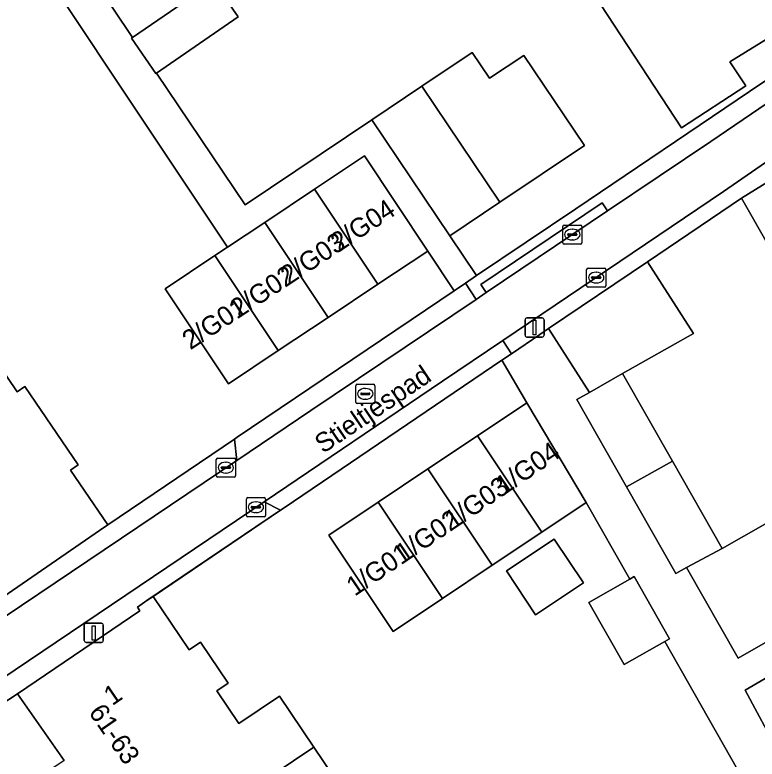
# Model space of a CAD drawing. Extents: x 159888 to 160761, y 384031 to 384750.
# Drawn here: x 160437.78 to 160476.49, y 384295.49 to 384334.29 of the extents above; entities that cross this region are included whole.
import ezdxf

# ---------------------------------------------------------------- set-up
doc = ezdxf.new("R2010")
doc.units = 0
for name, color, linetype in [('IMGEO_Erf', 7, 'Continuous'), ('IMGEO_Kolk', 7, 'Continuous'), ('IMGEO_Lichtmast', 7, 'Continuous'), ('IMGEO_Muur', 7, 'Continuous'), ('IMGEO_Openbare_ruimte_label', 7, 'Continuous'), ('IMGEO_Pand', 7, 'Continuous'), ('IMGEO_Pand_nummerreeks', 7, 'Continuous'), ('IMGEO_Rijbaan_lokaal_open', 7, 'Continuous'), ('IMGEO_Rioolput', 7, 'Continuous'), ('IMGEO_Voetpad_open', 7, 'Continuous')]:
    doc.layers.add(name, color=color, linetype=linetype)

msp = doc.modelspace()

# ---------------------------------------------------------------- linework, layer by layer
at = {"layer": 'IMGEO_Erf'}
for points in [[(160456.666, 384356.276), (160458.578, 384353.848), (160460.552, 384351.342), (160461.672, 384352.224), (160468.506, 384356.754), (160471.872, 384351.597), (160475.173, 384346.539), (160478.474, 384341.481), (160481.974, 384336.119), (160475.071, 384331.85), (160475.896, 384330.595), (160472.553, 384328.397), (160468.334, 384334.813), (160471.677, 384337.011), (160468.359, 384342.057), (160465.04, 384347.104), (160461.502, 384344.777), (160458.334, 384349.595), (160454.817, 384346.825), (160452.803, 384349.382), (160452.769, 384349.425), (160446.476, 384344.469), (160444.638, 384346.803)], [(160487.032, 384315.964), (160485.504, 384318.66), (160484.117, 384321.107), (160479.288, 384318.371), (160478.097, 384320.473), (160477.012, 384322.387), (160475.678, 384324.741), (160470.773, 384321.422), (160473.178, 384317.676), (160469.475, 384315.595), (160472.079, 384311.028), (160474.675, 384306.475), (160478.184, 384308.475), (160480.847, 384303.804), (160490.773, 384309.494), (160489.194, 384312.28), (160484.426, 384309.578), (160484.38, 384309.552), (160482.675, 384308.586), (160481.62, 384310.447), (160483.325, 384311.413), (160482.275, 384313.267)], [(160492.415, 384304.215), (160490.486, 384307.61), (160475.868, 384299.074), (160477.633, 384295.818), (160478.853, 384296.511)], [(160464.938, 384303.017), (160463.416, 384305.296), (160465.906, 384306.959), (160467.429, 384304.681)]]:
    msp.add_lwpolyline(points, close=True, dxfattribs=at)
for points in [[(160434.938, 384346.488), (160443.918, 384333.117), (160448.156, 384336.03), (160449.423, 384334.187), (160445.166, 384331.26), (160449.784, 384324.384), (160456.397, 384328.826), (160459.01, 384330.581), (160461.626, 384332.337), (160462.527, 384330.994), (160464.329, 384332.179), (160467.485, 384327.479), (160463.08, 384324.521), (160460.466, 384322.766), (160461.863, 384320.697), (160467.03, 384324.187), (160476.088, 384330.303), (160483.657, 384335.415)], [(160436.409, 384316.824), (160437.899, 384314.639), (160438.308, 384314.912), (160441.08, 384310.832), (160440.677, 384310.562), (160442.622, 384307.708), (160449.231, 384312.166), (160449.382, 384312.268), (160460.694, 384319.908), (160459.314, 384321.98), (160456.715, 384320.249), (160454.116, 384318.518), (160451.516, 384316.786), (160448.917, 384315.055), (160445.615, 384320.013), (160448.214, 384321.744), (160448.878, 384322.186), (160435.234, 384342.622)], [(160482.685, 384282.232), (160471.687, 384301.627), (160469.561, 384300.415), (160467.711, 384303.659), (160469.845, 384304.875), (160467.581, 384308.868), (160465.262, 384307.319), (160462.677, 384305.592), (160460.091, 384303.865), (160457.506, 384302.138), (160454.148, 384307.164), (160456.734, 384308.891), (160459.319, 384310.618), (160461.905, 384312.346), (160464.49, 384314.073), (160463.178, 384316.282), (160451.825, 384308.598), (160451.63, 384308.466), (160444.987, 384303.97), (160446.868, 384301.186), (160447.463, 384301.589), (160448.908, 384299.452), (160448.312, 384299.049), (160449.468, 384297.338), (160451.59, 384298.767), (160453.375, 384296.116), (160454.889, 384293.868)], [(160440.346, 384295.421), (160437.919, 384298.895), (160432.977, 384295.669), (160463.867, 384250)]]:
    msp.add_lwpolyline(points, dxfattribs=at)
at = {"layer": 'IMGEO_Kolk'}
for p, q in [((160466.428, 384323.336), (160467.28, 384323.336)), ((160466.353, 384322.41), (160466.353, 384323.262)), ((160466.841, 384323.116), (160466.866, 384323.116)), ((160467.354, 384323.262), (160467.354, 384322.41)), ((160466.612, 384322.83), (160466.612, 384322.842)), ((160467.05, 384322.793), (160466.652, 384322.793)), ((160466.655, 384322.879), (160467.053, 384322.879)), ((160466.864, 384322.556), (160466.839, 384322.556)), ((160467.096, 384322.842), (160467.096, 384322.83)), ((160467.28, 384322.336), (160466.428, 384322.336)), ((160467.601, 384320.167), (160467.601, 384321.019)), ((160467.676, 384321.093), (160468.528, 384321.093)), ((160468.602, 384321.019), (160468.602, 384320.167)), ((160467.86, 384320.587), (160467.86, 384320.599)), ((160467.903, 384320.636), (160468.301, 384320.636)), ((160468.089, 384320.873), (160468.114, 384320.873)), ((160468.344, 384320.599), (160468.344, 384320.587)), ((160468.298, 384320.55), (160467.9, 384320.55)), ((160468.112, 384320.313), (160468.087, 384320.313)), ((160468.528, 384320.093), (160467.676, 384320.093)), ((160448.284, 384310.259), (160448.284, 384311.111)), ((160448.359, 384311.185), (160449.211, 384311.185)), ((160448.772, 384310.965), (160448.797, 384310.965)), ((160449.285, 384311.111), (160449.285, 384310.259)), ((160448.543, 384310.679), (160448.543, 384310.691)), ((160448.981, 384310.642), (160448.583, 384310.642)), ((160448.586, 384310.728), (160448.984, 384310.728)), ((160449.027, 384310.691), (160449.027, 384310.679)), ((160449.211, 384310.185), (160448.359, 384310.185)), ((160448.795, 384310.405), (160448.77, 384310.405)), ((160449.853, 384308.194), (160449.853, 384309.046)), ((160449.928, 384309.12), (160450.78, 384309.12)), ((160450.854, 384309.046), (160450.854, 384308.194)), ((160450.112, 384308.614), (160450.112, 384308.626)), ((160450.55, 384308.577), (160450.152, 384308.577)), ((160450.155, 384308.663), (160450.553, 384308.663)), ((160450.341, 384308.9), (160450.366, 384308.9)), ((160450.596, 384308.626), (160450.596, 384308.614)), ((160450.364, 384308.34), (160450.339, 384308.34)), ((160450.78, 384308.12), (160449.928, 384308.12))]:
    msp.add_line(p, q, dxfattribs=at)
for points in [[(160466.428, 384323.336), (160467.28, 384323.336)], [(160466.353, 384322.41), (160466.353, 384323.262)], [(160467.354, 384323.262), (160467.354, 384322.41)], [(160467.28, 384322.336), (160466.428, 384322.336)], [(160467.601, 384320.167), (160467.601, 384321.019)], [(160467.676, 384321.093), (160468.528, 384321.093)], [(160468.602, 384321.019), (160468.602, 384320.167)], [(160468.528, 384320.093), (160467.676, 384320.093)], [(160448.284, 384310.259), (160448.284, 384311.111)], [(160448.359, 384311.185), (160449.211, 384311.185)], [(160449.285, 384311.111), (160449.285, 384310.259)], [(160449.211, 384310.185), (160448.359, 384310.185)], [(160449.853, 384308.194), (160449.853, 384309.046)], [(160449.928, 384309.12), (160450.78, 384309.12)], [(160450.854, 384309.046), (160450.854, 384308.194)], [(160450.78, 384308.12), (160449.928, 384308.12)]]:
    msp.add_lwpolyline(points, dxfattribs=at)
for centre, radius, start, end in [((160466.43, 384323.26), 0.0765, 91.552, 178.448), ((160466.43, 384323.26), 0.0765, 91.552, 178.448), ((160467.278, 384323.26), 0.0765, 1.552, 88.448), ((160467.278, 384323.26), 0.0765, 1.552, 88.448), ((160466.652, 384322.839), 0.0403, 85.8775, 175.7526), ((160466.649, 384322.829), 0.0366, 178.938, 274.7102), ((160467.053, 384322.836), 0.043, 264.8664, 352.4533), ((160467.057, 384322.841), 0.0386, 1.7309, 96.639), ((160466.43, 384322.412), 0.0765, 181.552, 268.448), ((160466.43, 384322.412), 0.0765, 181.552, 268.448), ((160467.278, 384322.412), 0.0765, 271.552, 358.448), ((160467.278, 384322.412), 0.0765, 271.552, 358.448), ((160467.678, 384321.017), 0.0765, 91.552, 178.448), ((160467.678, 384321.017), 0.0765, 91.552, 178.448), ((160468.526, 384321.017), 0.0765, 1.552, 88.448), ((160468.526, 384321.017), 0.0765, 1.552, 88.448), ((160467.9, 384320.596), 0.0403, 85.8775, 175.7526), ((160467.897, 384320.586), 0.0366, 178.938, 274.7102), ((160468.301, 384320.593), 0.043, 264.8664, 352.4533), ((160468.305, 384320.598), 0.0386, 1.7309, 96.639), ((160467.678, 384320.169), 0.0765, 181.552, 268.448), ((160467.678, 384320.169), 0.0765, 181.552, 268.448), ((160468.526, 384320.169), 0.0765, 271.552, 358.448), ((160468.526, 384320.169), 0.0765, 271.552, 358.448), ((160448.361, 384311.109), 0.0765, 91.552, 178.448), ((160448.361, 384311.109), 0.0765, 91.552, 178.448), ((160449.209, 384311.109), 0.0765, 1.552, 88.448), ((160449.209, 384311.109), 0.0765, 1.552, 88.448), ((160448.583, 384310.688), 0.0403, 85.8775, 175.7526), ((160448.58, 384310.678), 0.0366, 178.938, 274.7102), ((160448.984, 384310.685), 0.043, 264.8664, 352.4533), ((160448.988, 384310.69), 0.0386, 1.7309, 96.639), ((160448.361, 384310.261), 0.0765, 181.552, 268.448), ((160448.361, 384310.261), 0.0765, 181.552, 268.448), ((160449.209, 384310.261), 0.0765, 271.552, 358.448), ((160449.209, 384310.261), 0.0765, 271.552, 358.448), ((160449.93, 384309.044), 0.0765, 91.552, 178.448), ((160449.93, 384309.044), 0.0765, 91.552, 178.448), ((160450.778, 384309.044), 0.0765, 1.552, 88.448), ((160450.778, 384309.044), 0.0765, 1.552, 88.448), ((160450.152, 384308.623), 0.0403, 85.8775, 175.7526), ((160450.149, 384308.613), 0.0366, 178.938, 274.7102), ((160450.553, 384308.62), 0.043, 264.8664, 352.4533), ((160450.557, 384308.625), 0.0386, 1.7309, 96.639), ((160449.93, 384308.196), 0.0765, 181.552, 268.448), ((160449.93, 384308.196), 0.0765, 181.552, 268.448), ((160450.778, 384308.196), 0.0765, 271.552, 358.448), ((160450.778, 384308.196), 0.0765, 271.552, 358.448)]:
    msp.add_arc(centre, radius, start, end, dxfattribs=at)
for centre, major_axis, ratio, start_param, end_param in [((160466.84, 384322.836), (-0.387, 0.002), 0.722429, 4.712389, 7.853982), ((160466.865, 384322.836), (-0.39, 0.002), 0.717154, 1.570796, 4.712389), ((160468.088, 384320.593), (-0.387, 0.002), 0.722429, 4.712389, 7.853982), ((160468.113, 384320.593), (-0.39, 0.002), 0.717154, 1.570796, 4.712389), ((160448.771, 384310.685), (-0.387, 0.002), 0.722429, 4.712389, 7.853982), ((160448.796, 384310.685), (-0.39, 0.002), 0.717154, 1.570796, 4.712389), ((160450.34, 384308.62), (-0.387, 0.002), 0.722429, 4.712389, 7.853982), ((160450.365, 384308.62), (-0.39, 0.002), 0.717154, 1.570796, 4.712389)]:
    msp.add_ellipse(centre, major_axis=major_axis, ratio=ratio, start_param=start_param, end_param=end_param, dxfattribs=at)
at = {"layer": 'IMGEO_Lichtmast'}
for p, q in [((160464.387, 384317.593), (160464.387, 384318.393)), ((160464.387, 384318.393), (160464.387, 384317.593)), ((160464.487, 384318.493), (160465.277, 384318.493)), ((160465.277, 384318.493), (160464.487, 384318.493)), ((160465.377, 384318.393), (160465.377, 384317.593)), ((160465.377, 384317.593), (160465.377, 384318.393)), ((160465.277, 384317.493), (160464.487, 384317.493)), ((160464.487, 384317.493), (160465.277, 384317.493)), ((160441.4, 384301.669), (160441.4, 384302.469)), ((160441.4, 384302.469), (160441.4, 384301.669)), ((160441.5, 384302.569), (160442.29, 384302.569)), ((160442.29, 384302.569), (160441.5, 384302.569)), ((160442.39, 384302.469), (160442.39, 384301.669)), ((160442.39, 384301.669), (160442.39, 384302.469)), ((160442.29, 384301.569), (160441.5, 384301.569)), ((160441.5, 384301.569), (160442.29, 384301.569))]:
    msp.add_line(p, q, dxfattribs=at)
for points in [[(160464.807, 384318.368), (160464.957, 384318.368), (160464.957, 384317.618), (160464.807, 384317.618), (160464.807, 384318.368)], [(160441.82, 384302.444), (160441.97, 384302.444), (160441.97, 384301.694), (160441.82, 384301.694), (160441.82, 384302.444)]]:
    msp.add_lwpolyline(points, dxfattribs=at)
for centre, start, end in [((160464.487, 384318.393), 90, 180), ((160464.487, 384318.393), 90, 180), ((160465.277, 384318.393), 0, 90), ((160465.277, 384318.393), 360, 90), ((160464.487, 384317.593), 180, 270), ((160464.487, 384317.593), 180, 270), ((160465.277, 384317.593), 270, 0), ((160465.277, 384317.593), 270, 0), ((160441.5, 384302.469), 90, 180), ((160441.5, 384302.469), 90, 180), ((160442.29, 384302.469), 0, 90), ((160442.29, 384302.469), 360, 90), ((160441.5, 384301.669), 180, 270), ((160441.5, 384301.669), 180, 270), ((160442.29, 384301.669), 270, 0), ((160442.29, 384301.669), 270, 0)]:
    msp.add_arc(centre, 0.1, start, end, dxfattribs=at)
at = {"layer": 'IMGEO_Muur'}
for points in [[(160476.088, 384330.303), (160467.03, 384324.187)], [(160465.616, 384317.932), (160475.678, 384324.741)], [(160449.231, 384312.166), (160442.188, 384307.409)], [(160449.382, 384312.268), (160449.231, 384312.166)], [(160451.825, 384308.598), (160451.63, 384308.466)], [(160451.63, 384308.466), (160444.669, 384303.755)]]:
    msp.add_lwpolyline(points, dxfattribs=at)
at = {"layer": 'IMGEO_Pand'}
for points in [[(160481.974, 384336.119), (160478.474, 384341.481), (160471.677, 384337.011), (160468.334, 384334.813), (160472.553, 384328.397), (160475.896, 384330.595), (160475.071, 384331.85)], [(160443.918, 384333.117), (160443.863, 384333.079), (160445.13, 384331.236), (160445.166, 384331.26), (160449.423, 384334.187), (160448.156, 384336.03)], [(160464.329, 384332.179), (160462.527, 384330.994), (160461.626, 384332.337), (160459.01, 384330.581), (160463.08, 384324.521), (160467.485, 384327.479)], [(160488.821, 384326.551), (160486.16, 384331.218), (160475.678, 384324.741), (160477.012, 384322.387), (160478.097, 384320.473)], [(160459.01, 384330.581), (160456.397, 384328.826), (160460.466, 384322.766), (160463.08, 384324.521)], [(160456.715, 384320.249), (160459.314, 384321.98), (160456.012, 384326.938), (160453.413, 384325.207)], [(160456.715, 384320.249), (160453.413, 384325.207), (160450.813, 384323.475), (160454.116, 384318.518)], [(160450.813, 384323.475), (160448.878, 384322.186), (160448.214, 384321.744), (160451.516, 384316.786), (160454.116, 384318.518)], [(160451.516, 384316.786), (160448.214, 384321.744), (160445.615, 384320.013), (160448.917, 384315.055)], [(160470.773, 384321.422), (160465.616, 384317.932), (160467.742, 384314.607), (160469.475, 384315.595), (160473.178, 384317.676)], [(160440.677, 384310.562), (160441.08, 384310.832), (160438.308, 384314.912), (160437.899, 384314.639), (160436.409, 384316.824), (160435.975, 384316.528), (160429.151, 384311.879), (160431.649, 384308.311), (160429.254, 384306.635), (160430.513, 384304.836), (160432.802, 384306.438), (160435.399, 384302.726), (160442.188, 384307.409), (160442.622, 384307.708)], [(160469.475, 384315.595), (160467.742, 384314.607), (160467.087, 384314.233), (160469.677, 384309.691), (160472.079, 384311.028)], [(160461.905, 384312.346), (160465.262, 384307.319), (160467.581, 384308.868), (160464.49, 384314.073)], [(160459.319, 384310.618), (160462.677, 384305.592), (160465.262, 384307.319), (160461.905, 384312.346)], [(160472.079, 384311.028), (160469.677, 384309.691), (160472.258, 384305.163), (160472.807, 384305.476), (160474.675, 384306.475)], [(160459.319, 384310.618), (160456.734, 384308.891), (160460.091, 384303.865), (160462.677, 384305.592)], [(160456.734, 384308.891), (160454.148, 384307.164), (160457.506, 384302.138), (160460.091, 384303.865)], [(160472.807, 384305.476), (160475.499, 384300.755), (160480.847, 384303.804), (160478.184, 384308.475), (160474.675, 384306.475)], [(160463.416, 384305.296), (160464.938, 384303.017), (160467.429, 384304.681), (160465.906, 384306.959)], [(160469.845, 384304.875), (160467.711, 384303.659), (160469.561, 384300.415), (160471.687, 384301.627), (160471.922, 384301.761), (160470.073, 384305.005)], [(160444.987, 384303.97), (160444.669, 384303.755), (160444.17, 384303.417), (160444.305, 384303.218), (160437.919, 384298.895), (160440.346, 384295.421), (160438.045, 384293.867), (160439.388, 384291.879), (160441.639, 384293.399), (160444.047, 384289.833), (160450.934, 384294.472), (160451.258, 384294.69), (160453.375, 384296.116), (160451.59, 384298.767), (160449.468, 384297.338), (160448.312, 384299.049), (160448.908, 384299.452), (160447.463, 384301.589), (160446.868, 384301.186)], [(160453.375, 384296.116), (160451.258, 384294.69), (160450.934, 384294.472), (160444.047, 384289.833), (160446.455, 384286.268), (160444.223, 384284.76), (160445.558, 384282.783), (160447.789, 384284.29), (160450.211, 384280.704), (160457.418, 384285.573), (160455.676, 384288.151), (160454.306, 384290.179), (160454.856, 384290.551), (160453.326, 384292.816), (160454.889, 384293.868)]]:
    msp.add_lwpolyline(points, close=True, dxfattribs=at)
at = {"layer": 'IMGEO_Rijbaan_lokaal_open'}
for points in [[(160482.897, 384333.68), (160474.075, 384327.692), (160468.686, 384324.069), (160462.364, 384319.818), (160461.832, 384319.461), (160453.217, 384313.669), (160449.351, 384311.065), (160432.095, 384299.442), (160430.906, 384298.646), (160428.629, 384297.152), (160431.13, 384293.34)], [(160431.199, 384295.45), (160431.305, 384295.608), (160431.426, 384295.756), (160431.559, 384295.893), (160431.704, 384296.017), (160431.86, 384296.128), (160432.401, 384296.495), (160437.04, 384299.637), (160450.775, 384308.907), (160460.087, 384315.192), (160463.235, 384317.314), (160474.747, 384325.076), (160485.242, 384332.327)]]:
    msp.add_lwpolyline(points, dxfattribs=at)
at = {"layer": 'IMGEO_Rioolput'}
for p, q in [((160455.557, 384314.107), (160455.557, 384314.959)), ((160455.632, 384315.033), (160456.484, 384315.033)), ((160456.045, 384314.813), (160456.07, 384314.813)), ((160456.558, 384314.959), (160456.558, 384314.107)), ((160455.816, 384314.527), (160455.816, 384314.539)), ((160456.254, 384314.49), (160455.856, 384314.49)), ((160455.859, 384314.576), (160456.257, 384314.576)), ((160456.3, 384314.539), (160456.3, 384314.527)), ((160456.484, 384314.033), (160455.632, 384314.033)), ((160456.068, 384314.253), (160456.043, 384314.253))]:
    msp.add_line(p, q, dxfattribs=at)
for points in [[(160455.557, 384314.107), (160455.557, 384314.959)], [(160455.632, 384315.033), (160456.484, 384315.033)], [(160456.558, 384314.959), (160456.558, 384314.107)], [(160456.484, 384314.033), (160455.632, 384314.033)]]:
    msp.add_lwpolyline(points, dxfattribs=at)
for centre, radius, start, end in [((160455.634, 384314.957), 0.0765, 91.552, 178.448), ((160455.634, 384314.957), 0.0765, 91.552, 178.448), ((160456.482, 384314.957), 0.0765, 1.552, 88.448), ((160456.482, 384314.957), 0.0765, 1.552, 88.448), ((160455.856, 384314.536), 0.0403, 85.8775, 175.7526), ((160455.853, 384314.526), 0.0366, 178.938, 274.7102), ((160456.257, 384314.533), 0.043, 264.8664, 352.4533), ((160456.261, 384314.538), 0.0386, 1.7309, 96.639), ((160455.634, 384314.109), 0.0765, 181.552, 268.448), ((160455.634, 384314.109), 0.0765, 181.552, 268.448), ((160456.482, 384314.109), 0.0765, 271.552, 358.448), ((160456.482, 384314.109), 0.0765, 271.552, 358.448)]:
    msp.add_arc(centre, radius, start, end, dxfattribs=at)
for centre, major_axis, ratio, start_param, end_param in [((160456.044, 384314.533), (-0.387, 0.002), 0.722429, 4.712389, 7.853982), ((160456.069, 384314.533), (-0.39, 0.002), 0.717154, 1.570796, 4.712389)]:
    msp.add_ellipse(centre, major_axis=major_axis, ratio=ratio, start_param=start_param, end_param=end_param, dxfattribs=at)
at = {"layer": 'IMGEO_Voetpad_open'}
for points in [[(160435.234, 384342.622), (160448.878, 384322.186), (160450.813, 384323.475), (160453.413, 384325.207), (160456.012, 384326.938), (160459.314, 384321.98), (160460.694, 384319.908), (160461.281, 384320.304), (160461.863, 384320.697), (160460.466, 384322.766), (160456.397, 384328.826), (160449.784, 384324.384), (160445.166, 384331.26), (160445.13, 384331.236), (160443.863, 384333.079), (160443.918, 384333.117), (160434.938, 384346.488)], [(160480.847, 384303.804), (160475.499, 384300.755), (160472.807, 384305.476), (160472.258, 384305.163), (160469.677, 384309.691), (160467.087, 384314.233), (160467.742, 384314.607), (160465.616, 384317.932), (160465.155, 384317.62), (160463.685, 384316.625), (160463.178, 384316.282), (160464.49, 384314.073), (160467.581, 384308.868), (160469.845, 384304.875), (160470.073, 384305.005), (160471.922, 384301.761), (160471.687, 384301.627), (160482.685, 384282.232)], [(160477.633, 384295.818), (160475.868, 384299.074), (160490.486, 384307.61)]]:
    msp.add_lwpolyline(points, dxfattribs=at)
for points in [[(160474.075, 384327.692), (160482.897, 384333.68), (160484.226, 384334.549), (160483.657, 384335.415), (160476.088, 384330.303), (160467.03, 384324.187), (160461.863, 384320.697), (160461.281, 384320.304), (160461.832, 384319.461), (160462.364, 384319.818), (160462.089, 384320.235), (160468.411, 384324.486), (160468.686, 384324.069)], [(160475.678, 384324.741), (160486.16, 384331.218), (160485.451, 384332.462), (160485.242, 384332.327), (160474.747, 384325.076), (160463.235, 384317.314), (160463.685, 384316.625), (160465.155, 384317.62), (160465.616, 384317.932), (160470.773, 384321.422)], [(160462.364, 384319.818), (160468.686, 384324.069), (160468.411, 384324.486), (160462.089, 384320.235)], [(160461.832, 384319.461), (160461.281, 384320.304), (160460.694, 384319.908), (160449.382, 384312.268), (160449.231, 384312.166), (160449.351, 384311.065), (160453.217, 384313.669)], [(160463.178, 384316.282), (160463.685, 384316.625), (160463.235, 384317.314), (160460.087, 384315.192), (160450.775, 384308.907), (160451.63, 384308.466), (160451.825, 384308.598)], [(160449.351, 384311.065), (160449.231, 384312.166), (160442.622, 384307.708), (160442.188, 384307.409), (160435.399, 384302.726), (160430.378, 384299.406), (160430.906, 384298.646), (160432.095, 384299.442)], [(160437.919, 384298.895), (160444.305, 384303.218), (160444.17, 384303.417), (160444.669, 384303.755), (160444.987, 384303.97), (160451.63, 384308.466), (160450.775, 384308.907), (160437.04, 384299.637), (160432.401, 384296.495), (160432.977, 384295.669)]]:
    msp.add_lwpolyline(points, close=True, dxfattribs=at)

# ---------------------------------------------------------------- texts
at = {"layer": 'IMGEO_Openbare_ruimte_label'}
msp.add_text('Stieltjespad', height=1, rotation=33.992, dxfattribs=at).set_placement((160453.854, 384311.394))
at = {"layer": 'IMGEO_Pand_nummerreeks'}
for s, rotation, p in [('2/G04', 33.4048, (160454.676, 384321.905)), ('2/G03', 33.4048, (160452.064, 384320.183)), ('2/G02', 33.4034, (160449.447, 384318.457)), ('2/G01', 33.4048, (160446.933, 384316.799)), ('1/G04', 34.1515, (160463.282, 384309.229)), ('1/G03', 34.1515, (160460.624, 384307.426)), ('1/G02', 34.1515, (160458.068, 384305.692)), ('1/G01', 34.1515, (160455.507, 384303.954)), ('1', 34.366, (160442.857, 384298.244)), ('61-63', 304.5835, (160441.596, 384297.927))]:
    msp.add_text(s, height=1, rotation=rotation, dxfattribs=at).set_placement(p)

doc.saveas('drawing.dxf')
